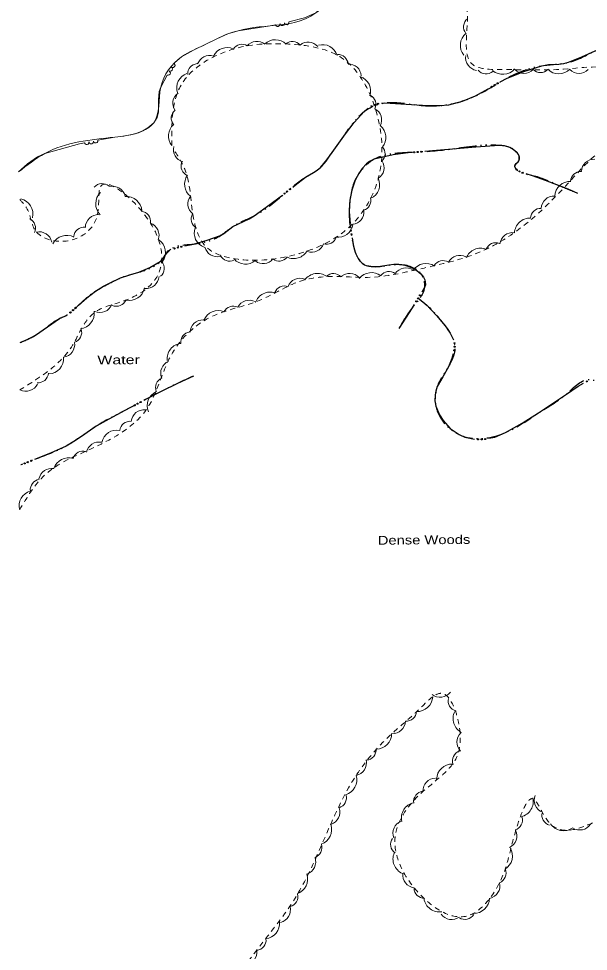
# Model space of a CAD drawing. Extents: x 2362213 to 2366494, y 6968794 to 6978110.
# Drawn here: x 2363819 to 2364129, y 6969918 to 6970425 of the extents above; entities that cross this region are included whole.
import ezdxf

# ---------------------------------------------------------------- set-up
doc = ezdxf.new("R2010")
doc.units = 0
doc.header["$LTSCALE"] = 1.9
doc.linetypes.add('DASH_DOUBLE_DOT', pattern=[9.2, 5, -1.2, 0.3, -1.2, 0.3, -1.2])
doc.linetypes.add('SHORT_DASHED', pattern=[2.7, 1.5, -1.2])
for name, color, linetype, lineweight in [('25', 7, 'Continuous', 25), ('29', 7, 'Continuous', 13), ('30', 7, 'Continuous', 13)]:
    doc.layers.add(name, color=color, linetype=linetype, lineweight=lineweight)

msp = doc.modelspace()

# ---------------------------------------------------------------- linework, layer by layer
at = {"layer": '25'}
msp.add_line((2363820.643, 6970182.595), (2363820.464, 6970182.524), dxfattribs=at)
for points in [[(2364081.77, 6970391.101), (2364084.794, 6970392.82), (2364094.328, 6970396.671), (2364104.109, 6970399.745), (2364107.713, 6970400.339), (2364113.251, 6970400.622), (2364115.978, 6970400.918), (2364118.621, 6970401.573), (2364125.903, 6970404.622), (2364133.154, 6970407.752), (2364138.295, 6970409.781)], [(2364016.86, 6970379.313), (2364018.588, 6970379.489), (2364027.272, 6970378.972), (2364035.959, 6970378.395), (2364042.242, 6970378.134), (2364048.523, 6970378.024), (2364053.518, 6970378.482), (2364060.861, 6970380.452), (2364068.024, 6970383.34), (2364074.946, 6970387.236)], [(2363968.572, 6970333.721), (2363969.842, 6970334.703), (2363975.471, 6970339.057), (2363979.726, 6970341.648), (2363981.843, 6970342.958), (2363983.738, 6970344.546), (2363986.981, 6970348.467), (2363989.943, 6970352.584), (2363993.565, 6970357.63), (2363997.187, 6970362.675), (2364001.898, 6970368.9), (2364007.321, 6970374.822), (2364009.594, 6970376.643)], [(2364032.596, 6970352.411), (2364023.197, 6970351.272), (2364012.86, 6970348.833), (2364010.26, 6970347.619), (2364008.552, 6970346.322), (2364006.326, 6970343.871), (2364004.373, 6970341.012), (2364002.468, 6970337.454), (2364000.559, 6970332.044), (2363999.582, 6970326.486), (2363999.249, 6970320.462), (2363999.653, 6970313.796)], [(2364089.41, 6970344.962), (2364089.4, 6970344.992), (2364089.426, 6970345.422), (2364089.612, 6970345.794), (2364090.176, 6970346.459), (2364091.196, 6970347.449), (2364091.572, 6970347.943), (2364091.747, 6970348.435), (2364091.789, 6970349.305), (2364091.762, 6970350.025), (2364091.667, 6970350.584), (2364091.379, 6970351.391), (2364090.832, 6970352.116), (2364088.453, 6970354.092), (2364086.612, 6970355.206), (2364083.763, 6970356.219), (2364080.781, 6970356.4), (2364068.07, 6970355.339), (2364055.36, 6970354.287), (2364044.497, 6970353.414), (2364040.41, 6970353.085)], [(2364123.672, 6970330.257), (2364118.38, 6970332.467), (2364113.06, 6970334.597), (2364106.024, 6970337.27), (2364098.969, 6970339.893), (2364095.629, 6970340.861)], [(2363909.734, 6970301.639), (2363914.464, 6970302.664), (2363921.875, 6970304.755), (2363929.141, 6970307.343), (2363930.911, 6970308.37), (2363935.784, 6970312.158), (2363941.698, 6970314.994), (2363944.675, 6970316.413), (2363947.479, 6970318.089), (2363955.902, 6970324.14), (2363962.336, 6970328.96)], [(2364000.757, 6970306.045), (2364001.432, 6970302.292), (2364002.098, 6970299.589), (2364002.717, 6970297.634), (2364004.082, 6970294.847), (2364005.065, 6970293.537), (2364006.307, 6970292.268), (2364007.535, 6970291.41), (2364008.489, 6970291.009), (2364009.962, 6970290.673), (2364011.465, 6970290.487), (2364015.145, 6970290.532), (2364020.697, 6970291.405), (2364023.474, 6970291.722), (2364026.235, 6970291.648), (2364029.409, 6970291.128), (2364031.715, 6970290.49), (2364035.031, 6970288.932), (2364038.235, 6970286.391), (2364039.622, 6970284.644), (2364040.316, 6970283.211), (2364040.616, 6970282.125), (2364040.661, 6970280.525), (2364040.175, 6970279.05), (2364038.69, 6970276.496)], [(2363851.748, 6970269.326), (2363851.966, 6970269.528), (2363856.421, 6970273.35), (2363861.027, 6970277.004), (2363865.49, 6970279.737), (2363870.157, 6970282.12), (2363872.437, 6970283.252), (2363874.757, 6970284.294), (2363879.733, 6970285.912), (2363884.759, 6970287.4), (2363890.633, 6970289.987), (2363896.234, 6970293.13), (2363897.077, 6970293.808), (2363898.242, 6970295.38), (2363899.789, 6970297.974), (2363900.719, 6970299.043), (2363901.902, 6970299.755), (2363902.111, 6970299.807)], [(2364036.681, 6970273.237), (2364039.279, 6970271.311), (2364041.679, 6970269.174), (2364046.68, 6970263.841), (2364051.363, 6970258.226), (2364052.812, 6970256.26), (2364054.142, 6970254.152), (2364055.844, 6970250.938), (2364055.957, 6970250.599)], [(2364034.643, 6970269.777), (2364033.491, 6970267.926), (2364029.913, 6970262.341), (2364026.277, 6970256.797)], [(2363820.019, 6970249.153), (2363824.342, 6970250.924), (2363828.442, 6970253.073), (2363834.96, 6970257.585), (2363841.396, 6970262.126), (2363842.66, 6970262.778), (2363844.663, 6970263.597), (2363845.618, 6970264.076), (2363845.817, 6970264.208)], [(2364055.88, 6970242.947), (2364055.075, 6970240.329), (2364053.195, 6970235.942), (2364050.148, 6970230.493), (2364047.149, 6970225.154), (2364046.283, 6970222.586), (2364045.913, 6970220.551), (2364045.852, 6970217.441), (2364046.431, 6970214.416), (2364048.375, 6970209.785), (2364050.386, 6970206.574), (2364054.235, 6970202.351), (2364059.059, 6970198.975), (2364062.112, 6970197.614), (2364067.393, 6970196.475)], [(2363914.377, 6970230.87), (2363905.726, 6970226.858), (2363897.165, 6970222.656), (2363888.229, 6970218.03), (2363887.463, 6970217.622)], [(2364075.168, 6970196.959), (2364078.433, 6970197.58), (2364084.23, 6970200.046), (2364093.37, 6970205.254), (2364102.328, 6970210.839), (2364109.859, 6970215.95), (2364117.451, 6970221.073), (2364123.891, 6970225.275), (2364126.795, 6970226.943)], [(2363880.538, 6970213.956), (2363879.334, 6970213.315), (2363870.379, 6970208.45), (2363861.477, 6970203.495), (2363853.368, 6970197.997), (2363849.354, 6970195.178), (2363845.117, 6970192.738), (2363836.564, 6970188.906), (2363827.946, 6970185.435)]]:
    msp.add_lwpolyline(points, dxfattribs=at)
for centre in [(2364076.684, 6970388.215), (2364078.354, 6970389.163), (2364080.023, 6970390.111), (2364011.304, 6970377.663), (2364013.067, 6970378.407), (2364014.879, 6970379.041), (2364034.588, 6970352.608), (2364036.502, 6970352.763), (2364038.416, 6970352.918), (2364090.329, 6970343.212), (2364091.955, 6970342.212), (2364093.718, 6970341.465), (2363965.457, 6970331.326), (2363966.978, 6970332.498), (2363963.934, 6970330.157), (2363999.772, 6970311.804), (2364000.06, 6970309.908), (2364000.4, 6970308.018), (2363905.919, 6970300.745), (2363907.783, 6970301.205), (2363904.055, 6970300.285), (2364035.702, 6970271.483), (2364036.716, 6970273.114), (2364037.69, 6970274.768), (2363847.389, 6970265.442), (2363848.834, 6970266.707), (2363850.264, 6970267.988), (2364056.447, 6970244.866), (2364056.513, 6970248.684), (2364056.603, 6970246.78), (2364128.528, 6970227.934), (2363882.305, 6970214.89), (2363884.002, 6970215.789), (2363885.698, 6970216.689), (2364069.377, 6970196.391), (2364071.297, 6970196.38), (2364073.197, 6970196.586), (2363824.297, 6970183.994), (2363826.083, 6970184.698), (2363822.505, 6970183.306)]:
    msp.add_circle(centre, 0.3, dxfattribs=at)
at = {"layer": '25', "linetype": 'DASH_DOUBLE_DOT'}
for points in [[(2363820.019, 6970249.153), (2363828.442, 6970253.073), (2363841.396, 6970262.126), (2363846.503, 6970264.664), (2363851.966, 6970269.528), (2363861.027, 6970277.004), (2363870.157, 6970282.12), (2363874.757, 6970284.294), (2363884.759, 6970287.4), (2363896.234, 6970293.13), (2363901.902, 6970299.755), (2363914.464, 6970302.664), (2363929.141, 6970307.343), (2363935.784, 6970312.158), (2363947.479, 6970318.089), (2363964.202, 6970330.358), (2363975.471, 6970339.057), (2363983.738, 6970344.546), (2363989.943, 6970352.584), (2363997.187, 6970362.675), (2364007.321, 6970374.822), (2364018.588, 6970379.489), (2364035.959, 6970378.395), (2364048.523, 6970378.024), (2364068.024, 6970383.34), (2364084.794, 6970392.82), (2364104.109, 6970399.745), (2364118.621, 6970401.573), (2364133.154, 6970407.752), (2364147.806, 6970412.821), (2364164.699, 6970415.782), (2364183.268, 6970419.139), (2364197.688, 6970422.368), (2364209.57, 6970427.56), (2364212.094, 6970428.034)], [(2364123.672, 6970330.257), (2364113.06, 6970334.597), (2364098.969, 6970339.893), (2364090.891, 6970342.746), (2364089.4, 6970344.992), (2364091.747, 6970348.435), (2364090.832, 6970352.116), (2364080.781, 6970356.4), (2364055.36, 6970354.287), (2364033.635, 6970352.53), (2364012.86, 6970348.833), (2364004.373, 6970341.012), (2363999.582, 6970326.486), (2364001.432, 6970302.292), (2364006.307, 6970292.268), (2364011.465, 6970290.487), (2364026.235, 6970291.648), (2364038.235, 6970286.391), (2364040.175, 6970279.05), (2364033.491, 6970267.926), (2364026.277, 6970256.797)], [(2364036.681, 6970273.237), (2364041.679, 6970269.174), (2364051.363, 6970258.226), (2364054.142, 6970254.152), (2364056.675, 6970247.666), (2364053.195, 6970235.942), (2364047.149, 6970225.154), (2364046.431, 6970214.416), (2364059.059, 6970198.975), (2364084.23, 6970200.046), (2364102.328, 6970210.839), (2364117.451, 6970221.073), (2364130.366, 6970228.987), (2364137.977, 6970224.749), (2364149.408, 6970205.767), (2364158.474, 6970180.032), (2364164.598, 6970165.93), (2364169.086, 6970155.702), (2364168.749, 6970146.978), (2364168.993, 6970133.95), (2364173.253, 6970124.5), (2364181.423, 6970111.928)], [(2363914.377, 6970230.87), (2363897.165, 6970222.656), (2363879.334, 6970213.315), (2363861.477, 6970203.495), (2363845.117, 6970192.738), (2363827.876, 6970185.404), (2363820.464, 6970182.524)]]:
    msp.add_spline(points, degree=3, dxfattribs=at)
at = {"layer": '29'}
for centre, radius, start, end in [((2364067.143, 6970420.928), 5.671, 129.11814, 219.11814), ((2363948.977, 6970406.201), 6.814, 51.12714, 141.12714), ((2363958.978, 6970405.713), 8.172, 44.42216, 134.42216), ((2363968.265, 6970407.462), 5.445, 40.15535, 130.15535), ((2364068.209, 6970410.809), 8.512, 129.11814, 219.11814), ((2363932.678, 6970401.447), 8.172, 64.44844, 154.44844), ((2363940.815, 6970405.945), 5.445, 58.97698, 148.97698), ((2363976.845, 6970405.767), 6.814, 40.15535, 130.15535), ((2363984.769, 6970403.014), 8.172, 16.79883, 106.79883), ((2363923.114, 6970398.454), 6.814, 71.03864, 161.03864), ((2363993.104, 6970400.372), 5.445, 3.15005, 93.15005), ((2364069.676, 6970404.155), 7.096, 170.68617, 260.68617), ((2363916.734, 6970395.416), 5.445, 93.98476, 183.98476), ((2363998.936, 6970393.854), 6.814, 3.15005, 93.15005), ((2364082.835, 6970403.544), 8.512, 229.25487, 319.25487), ((2364094.293, 6970402.643), 7.096, 225.32291, 315.32291), ((2364103.358, 6970401.686), 5.671, 225.25182, 315.25182), ((2364113.305, 6970403.827), 8.512, 225.25182, 315.25182), ((2364124.414, 6970402.644), 7.096, 224.50653, 314.50653), ((2363913.508, 6970387.743), 8.172, 109.31188, 199.31187), ((2364002.675, 6970386.052), 8.172, 340.76925, 70.76925), ((2364073.673, 6970400.985), 5.671, 220.47132, 310.47132), ((2363909.994, 6970379.344), 6.814, 125.66045, 215.66045), ((2364008.283, 6970378.73), 5.445, 333.04243, 63.04243), ((2363907.765, 6970371.206), 5.445, 130.10466, 220.10466), ((2364010.059, 6970370.166), 6.814, 333.04243, 63.04243), ((2363908.956, 6970361.509), 8.172, 130.10466, 220.10466), ((2364011.02, 6970360.759), 8.172, 320.26703, 50.26703), ((2363910.326, 6970354.017), 6.814, 165.11311, 255.11311), ((2364013.286, 6970351.928), 5.445, 312.50687, 42.50687), ((2363913.115, 6970345.082), 5.445, 157.52143, 247.52143), ((2364011.384, 6970344.211), 6.814, 302.41057, 32.41057), ((2364132.608, 6970341.86), 7.006, 87.53265, 177.53265), ((2364125.351, 6970336.547), 5.599, 87.53265, 177.53265), ((2363917.736, 6970335.199), 8.172, 143.09368, 233.09368), ((2364007.598, 6970335.053), 8.172, 294.59898, 24.59898), ((2364119.495, 6970328.37), 8.404, 87.41304, 177.41304), ((2363864.669, 6970329.88), 5.692, 48.56614, 138.56614), ((2363870.295, 6970326.981), 7.122, 13.0758, 103.0758), ((2363818.454, 6970318.957), 8.543, 346.79853, 76.79853), ((2363869.736, 6970324.655), 8.543, 134.48102, 224.48102), ((2363877.866, 6970319.999), 8.543, 4.63584, 94.63584), ((2363918.183, 6970324.544), 6.814, 143.03552, 233.03552), ((2364005.485, 6970326.313), 5.445, 286.20885, 16.20885), ((2364110.719, 6970321.815), 7.006, 87.41304, 177.41304), ((2364103.443, 6970316.518), 5.599, 87.32346, 177.32346), ((2363822.755, 6970311.322), 5.692, 334.54359, 64.54359), ((2363862.662, 6970311.559), 7.122, 88.26777, 178.26777), ((2363885.4, 6970314.865), 5.692, 353.06684, 83.06684), ((2363918.638, 6970316.275), 5.445, 149.39862, 239.39862), ((2364000.387, 6970320.194), 6.814, 276.35946, 6.35946), ((2364097.569, 6970308.367), 8.404, 87.32346, 177.32346), ((2363854.873, 6970306.171), 5.692, 84.0869, 174.0869), ((2363888.557, 6970307.334), 7.122, 340.71411, 70.71411), ((2363923.016, 6970308.655), 8.172, 159.76327, 249.76327), ((2363993.127, 6970314.533), 8.172, 261.13673, 351.13673), ((2363830.335, 6970302.25), 7.122, 12.27511, 102.27511), ((2363845.423, 6970298.873), 8.543, 62.56271, 152.56271), ((2363986.937, 6970307.988), 5.445, 251.17635, 341.17635), ((2364088.226, 6970301.917), 7.006, 83.06931, 173.06931), ((2363890.645, 6970298.06), 8.543, 324.52216, 54.52216), ((2363927.301, 6970302.602), 6.814, 193.63096, 283.63096), ((2363978.711, 6970305.018), 6.814, 251.17635, 341.17635), ((2364078.966, 6970297.809), 5.599, 68.26875, 158.26875), ((2363934.049, 6970298.834), 5.445, 206.02952, 296.02952), ((2363969.015, 6970302.915), 8.172, 242.59722, 332.59722), ((2364059.467, 6970289.528), 7.006, 62.35907, 152.35907), ((2364070.753, 6970292.022), 8.404, 68.26875, 158.26875), ((2363892.796, 6970289.461), 5.692, 310.52291, 40.52291), ((2363942.688, 6970299.911), 8.172, 220.97893, 310.97893), ((2363952.333, 6970298.809), 6.814, 231.54833, 321.54833), ((2363961.079, 6970298.843), 5.445, 231.54833, 321.54833), ((2364040.966, 6970283.694), 8.404, 56.0342, 146.0342), ((2364050.297, 6970288.048), 5.599, 58.49678, 148.49678), ((2363981.906, 6970278.314), 8.404, 54.06949, 144.06949), ((2363990.606, 6970281.036), 5.599, 42.94385, 132.94385), ((2363999.412, 6970279.721), 7.006, 41.88774, 131.88774), ((2364011.363, 6970278.776), 8.404, 52.68757, 142.68757), ((2364020.829, 6970282.144), 5.599, 52.68757, 142.68757), ((2364030.061, 6970282.668), 7.006, 56.0342, 146.0342), ((2363888.609, 6970285.659), 7.122, 264.82559, 354.82559), ((2363972.479, 6970277.062), 7.006, 69.30955, 159.30955), ((2363879.424, 6970280.499), 8.543, 258.49342, 348.49342), ((2363956.162, 6970268.147), 8.404, 71.44174, 161.44174), ((2363963.924, 6970274.285), 5.599, 69.30955, 159.30955), ((2363872.465, 6970274.508), 5.692, 246.69549, 336.69549), ((2363944.802, 6970265.093), 7.006, 63.07099, 153.07099), ((2363851.869, 6970265.062), 8.543, 276.86879, 6.86879), ((2363863.44, 6970272.518), 7.122, 247.31721, 337.31721), ((2363927.848, 6970258.055), 8.404, 67.40384, 157.40384), ((2363935.997, 6970263.262), 5.599, 63.07099, 153.07099), ((2363919.606, 6970254.433), 7.006, 87.94715, 177.94715), ((2363847.873, 6970254.616), 5.692, 288.09801, 18.09801), ((2363913.039, 6970249.261), 5.599, 96.44647, 186.44647), ((2363842.624, 6970248.076), 7.122, 278.72915, 8.72915), ((2363908.532, 6970240.282), 8.404, 96.44647, 186.44647), ((2363835.164, 6970240.507), 8.543, 273.61906, 3.61906), ((2363903.604, 6970232.503), 7.006, 113.06722, 203.06722), ((2363829.776, 6970232.874), 5.692, 264.80296, 354.80296), ((2363823.16, 6970229.683), 7.122, 243.25551, 333.25551), ((2363899.345, 6970224.581), 5.599, 113.06722, 203.06722), ((2363897.595, 6970214.688), 8.404, 113.06722, 203.06722), ((2363887.489, 6970205.461), 7.006, 83.79412, 173.79412), ((2363879.901, 6970200.633), 5.599, 83.79412, 173.79412), ((2363872.705, 6970193.036), 8.404, 78.38106, 168.38106), ((2363863.008, 6970187.94), 7.006, 78.38106, 168.38106), ((2363854.216, 6970184.384), 5.599, 72.50659, 162.50659), ((2363846.453, 6970178.007), 8.404, 72.50659, 162.50659), ((2363837.182, 6970173.574), 7.006, 79.31267, 169.31267), ((2363831.18, 6970169.003), 5.599, 97.43416, 187.43416), ((2363827.926, 6970160.184), 8.404, 105.11638, 195.11638), ((2364048.694, 6970063.148), 7.085, 231.86891, 321.86891), ((2364036.233, 6970056.788), 8.498, 266.92891, 356.92891), ((2364058.74, 6970054.044), 5.662, 165.9626, 255.9626), ((2364030.219, 6970048.693), 5.662, 266.0985, 356.0985), ((2364064.23, 6970044.462), 8.498, 153.22542, 243.22542), ((2364022.72, 6970043.309), 7.085, 267.84993, 357.84993), ((2364013.82, 6970036.249), 8.498, 270.79835, 0.79835), ((2364064.939, 6970031.674), 7.085, 134.46456, 224.46456), ((2364008.171, 6970027.399), 5.662, 275.71077, 5.71077), ((2364001.553, 6970020.462), 7.085, 281.84893, 11.84893), ((2364061.131, 6970021.446), 5.662, 110.0342, 200.0342), ((2364055.298, 6970011.221), 8.498, 88.76704, 178.76704), ((2363994.831, 6970011.071), 8.498, 286.9861, 16.9861), ((2364046.353, 6970004.992), 7.085, 91.41983, 181.41983), ((2363992.011, 6970001.311), 5.662, 286.9861, 16.9861), ((2364039.938, 6969999.278), 5.662, 98.03426, 188.03426), ((2364107.001, 6970000.096), 7.085, 158.75692, 248.75692), ((2364036.109, 6969990.384), 8.498, 102.96852, 192.96852), ((2364090.898, 6969999.311), 8.498, 283.6482, 13.6482), ((2363987.019, 6969993.588), 7.085, 288.42879, 18.42879), ((2364109.789, 6969991.844), 5.662, 163.82963, 253.82963), ((2363981.117, 6969984.11), 8.498, 289.36064, 19.36064), ((2364030.078, 6969981.98), 7.085, 110.61219, 200.61219), ((2364087.845, 6969989.195), 5.662, 288.05698, 18.05698), ((2364115.946, 6969991.911), 8.498, 213.71711, 303.71711), ((2364124.747, 6969990.904), 7.085, 236.30188, 326.30188), ((2364083.401, 6969980.705), 7.085, 294.88595, 24.88595), ((2364027.411, 6969975.992), 5.662, 144.72039, 234.72039), ((2363978.703, 6969974.241), 5.662, 289.36064, 19.36064), ((2364031.522, 6969967.946), 8.498, 156.49334, 246.49334), ((2364079.553, 6969969.661), 8.498, 301.97467, 31.97467), ((2363973.897, 6969966.566), 7.085, 288.89422, 18.89422), ((2364078.951, 6969960.375), 5.662, 291.5843, 21.5843), ((2363968.067, 6969957.152), 8.498, 288.89422, 18.89422), ((2364035.483, 6969959.388), 7.085, 172.88864, 262.88864), ((2364040.16, 6969952.258), 5.662, 180.34217, 270.34217), ((2364074.163, 6969953.485), 7.085, 282.83295, 12.83295), ((2363965.642, 6969947.652), 5.662, 284.0187, 14.0187), ((2364048.323, 6969947.738), 8.498, 189.04311, 279.04311), ((2364067.103, 6969946.933), 8.498, 268.07956, 358.07956), ((2363960.13, 6969940.418), 7.085, 284.0187, 14.0187), ((2364054.978, 6969942.179), 7.085, 216.00491, 306.00491), ((2364062.206, 6969940.843), 5.662, 237.78509, 327.78509), ((2363952.799, 6969932.987), 8.498, 276.61815, 6.61815), ((2363948.268, 6969923.894), 5.662, 276.61815, 6.61815), ((2363941.87, 6969917.43), 7.085, 276.61815, 6.61815)]:
    msp.add_arc(centre, radius, start, end, dxfattribs=at)
at = {"layer": '29', "linetype": 'SHORT_DASHED'}
for points in [[(2364124.196, 6970478.959), (2364147.8, 6970484.894), (2364176.747, 6970480.13), (2364202.921, 6970457.808), (2364208.05, 6970421.146), (2364201.881, 6970396.805), (2364178.261, 6970386.24), (2364149.005, 6970397.252), (2364113.789, 6970397.737), (2364084.949, 6970397.592), (2364065.917, 6970400.821), (2364063.547, 6970424.999), (2364063.816, 6970457.654), (2364091.588, 6970476.469), (2364123.939, 6970478.587)], [(2363902.634, 6970356.244), (2363907.711, 6970389.184), (2363934.808, 6970408.403), (2363966.141, 6970411.491), (2363994.047, 6970404.677), (2364015.004, 6970370.485), (2364014.884, 6970337.862), (2363998.03, 6970310.87), (2363967.897, 6970296.423), (2363943.368, 6970293.999), (2363921.005, 6970301.537), (2363914.29, 6970317.783), (2363909.677, 6970343.361), (2363903.147, 6970354.869)], [(2363819.747, 6970158.026), (2363833.428, 6970176.986), (2363859.818, 6970191.748), (2363889.175, 6970213.148), (2363902.004, 6970241.742), (2363923.176, 6970262.634), (2363951.045, 6970272.321), (2363972.181, 6970282.342), (2363989.376, 6970285.026), (2364009.131, 6970284.544), (2364040.025, 6970289.639), (2364067.833, 6970297.314), (2364089.729, 6970309.363), (2364116.874, 6970334.123), (2364142.838, 6970357.901), (2364162.086, 6970364.585), (2364191.414, 6970361.824), (2364204.329, 6970351.877), (2364204.017, 6970346.834), (2364196.865, 6970314.464), (2364198.103, 6970273.714), (2364205.818, 6970229.125), (2364210.955, 6970185.492), (2364223.99, 6970183.886), (2364240.264, 6970197.181), (2364241.582, 6970237.316), (2364247.956, 6970246.327), (2364255.782, 6970226.971), (2364254.29, 6970183.115), (2364251.704, 6970145.778), (2364250.854, 6970111.088)], [(2363819.899, 6970326.875), (2363823.959, 6970321.683), (2363827.894, 6970310.65), (2363841.806, 6970304.143), (2363861.958, 6970317.785), (2363863.795, 6970333.843), (2363890.507, 6970314.847), (2363893.449, 6970283.162), (2363875.32, 6970271.33), (2363860.517, 6970265.368), (2363853.095, 6970256.048), (2363849.245, 6970248.621), (2363819.945, 6970223.341)], [(2364250.854, 6970111.088), (2364250.316, 6970094.123), (2364252.614, 6970076.493), (2364259.507, 6970063.708), (2364266.192, 6970052.602), (2364271.238, 6970041.529), (2364272.619, 6970032.972), (2364268.61, 6970024.504), (2364264.416, 6970020.623), (2364256.62, 6970020.309), (2364249.038, 6970022.457), (2364240.913, 6970028.2), (2364228.953, 6970036.606), (2364218.794, 6970038.489), (2364212.167, 6970039.326), (2364215.413, 6970030.147), (2364219.209, 6970025.364), (2364230.62, 6970010.641), (2364231.024, 6969998.624), (2364213.759, 6970000.25), (2364192.176, 6970006.664), (2364176.691, 6970014.447), (2364168.765, 6970024.503), (2364167.614, 6970034.132), (2364154.837, 6970024.211), (2364151.467, 6970005.357), (2364132.261, 6969987.983), (2364108.578, 6969987.177), (2364098.958, 6970000.847), (2364090.551, 6969985.716), (2364080.875, 6969954.782), (2364063.403, 6969937.025), (2364035.446, 6969951.309), (2364024.447, 6969981.646), (2364038.425, 6970003.901), (2364057.17, 6970022.389), (2364058.963, 6970041.007), (2364049.319, 6970058.196), (2364037.538, 6970049.785), (2364020.999, 6970034.906), (2364003.219, 6970013.885), (2363987.998, 6969984.389), (2363969.707, 6969946.673), (2363945.082, 6969913.447), (2363917.442, 6969885.993), (2363892.302, 6969886.842), (2363864.918, 6969893.563), (2363837.547, 6969886.221), (2363819.381, 6969860.488)]]:
    msp.add_spline(points, degree=3, dxfattribs=at)
at = {"layer": '30'}
for points in [[(2363989.51, 6970469.476), (2363989.999, 6970468.531), (2363990.259, 6970467.415), (2363989.015, 6970459.511), (2363989.59, 6970451.556), (2363989.926, 6970443.61), (2363989.228, 6970439.172), (2363988.008, 6970435.931), (2363986.72, 6970433.668), (2363984.198, 6970430.684), (2363981.009, 6970428.424), (2363974.895, 6970425.805), (2363966.356, 6970423.534)], [(2363959.069, 6970422.024), (2363956.215, 6970421.447), (2363944.592, 6970419.666), (2363938.81, 6970418.671), (2363933.185, 6970417.058), (2363927.102, 6970414.38), (2363921.159, 6970411.413), (2363914.509, 6970408.15), (2363907.964, 6970404.557), (2363904.165, 6970401.321), (2363903.888, 6970400.958)], [(2363900.018, 6970394.631), (2363896.63, 6970388.068), (2363895.822, 6970385.771), (2363895.433, 6970381.407), (2363895.347, 6970374.645), (2363894.597, 6970371.498), (2363892.794, 6970368.701), (2363889.53, 6970365.93), (2363886.875, 6970364.364), (2363882.642, 6970362.714), (2363878.201, 6970361.692), (2363874.864, 6970361.26), (2363871.528, 6970360.838), (2363862.405, 6970359.141)], [(2363855.086, 6970357.781), (2363852.371, 6970357.276), (2363833.471, 6970351.994), (2363829.498, 6970350.147), (2363824.143, 6970346.396), (2363819.236, 6970341.899)]]:
    msp.add_lwpolyline(points, dxfattribs=at)
for centre, start, end in [((2363962.726, 6970422.756), 191.3651, 12.29667), ((2363965.158, 6970423.245), 190.44105, 11.36512), ((2363960.295, 6970422.267), 191.3651, 12.21386), ((2363901.728, 6970397.948), 242.70676, 63.63834), ((2363903.154, 6970399.971), 232.43178, 53.35585), ((2363900.591, 6970395.744), 242.70676, 63.55553), ((2363856.32, 6970358.008), 190.5429, 11.39167), ((2363858.759, 6970358.461), 190.5429, 11.47447), ((2363861.197, 6970358.915), 189.61886, 10.54292)]:
    msp.add_arc(centre, 1.24, start, end, dxfattribs=at)
msp.add_spline([(2363819.782, 6970459.91), (2363834.294, 6970459.898), (2363857.275, 6970465.097), (2363872.263, 6970469.52), (2363896.564, 6970469.511), (2363923.112, 6970468.904), (2363949.527, 6970468.576), (2363968.159, 6970471.523), (2363980.122, 6970472.257), (2363989.337, 6970469.815), (2363989.015, 6970459.511), (2363989.926, 6970443.61), (2363981.009, 6970428.424), (2363956.215, 6970421.447), (2363933.185, 6970417.058), (2363921.159, 6970411.413), (2363907.964, 6970404.557), (2363896.63, 6970388.068), (2363892.794, 6970368.701), (2363878.201, 6970361.692), (2363871.528, 6970360.838), (2363833.471, 6970351.994), (2363819.236, 6970341.899)], degree=3, dxfattribs=at)

# ---------------------------------------------------------------- texts
at = {"layer": '25', "width": 1.35}
msp.add_text('Water', height=4.8, rotation=0.546, dxfattribs=at).set_placement((2363862.116, 6970237.142))
at = {"layer": '29', "width": 1.25}
msp.add_text('Dense Woods', height=4.8, rotation=0.546, dxfattribs=at).set_placement((2364014.767, 6970139.052))

doc.saveas('drawing.dxf')
